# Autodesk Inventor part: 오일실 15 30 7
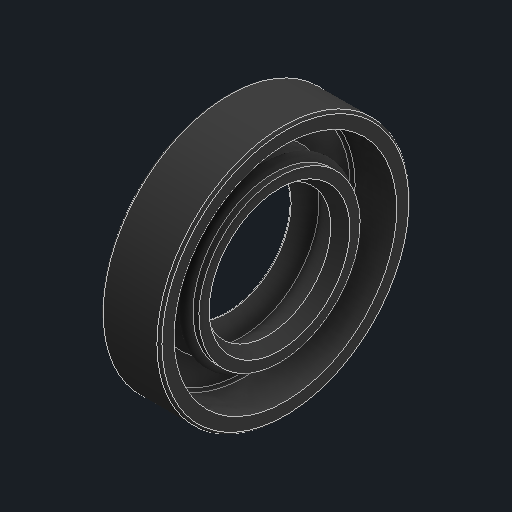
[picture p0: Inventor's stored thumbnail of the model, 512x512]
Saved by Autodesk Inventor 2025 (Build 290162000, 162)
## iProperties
Created: 2025-08
Part Number: 오일실 15 30 7
Material: 고무
Description: 오일-실
Document SubType Name: Modeling
Designer: infra012
Density: 0.93 g/cm^3
Appearance: 기본값
Author: jhkim
Sending System: Autodesk Inventor 2026
Preprocessor: ST-DEVELOPER v20.1
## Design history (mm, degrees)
sketch "스케치1"
  geometry: 1 further point
  constraints: 1 other
feature "Solid1"
node "솔리드1"
